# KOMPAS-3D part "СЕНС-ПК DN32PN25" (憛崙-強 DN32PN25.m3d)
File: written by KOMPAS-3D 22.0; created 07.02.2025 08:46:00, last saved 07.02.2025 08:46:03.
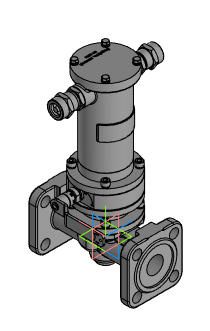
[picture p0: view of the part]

Document properties: Автор: setup; Полное имя файла: \\10.10.77.77\!! users\Савин А.Г\!Клапаны 3D для заказчика\СЕНС-ПК\1. СЕНС-ПК\СЕНС-ПК DN32PN25.m3d

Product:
- Body: Тело 1
    Масса: 11.446992
- Part/product: СЕНС-ПК DN32PN25
    Масса: 11.326737

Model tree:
1. Операция без истории:1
